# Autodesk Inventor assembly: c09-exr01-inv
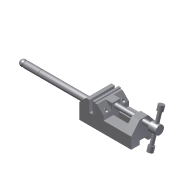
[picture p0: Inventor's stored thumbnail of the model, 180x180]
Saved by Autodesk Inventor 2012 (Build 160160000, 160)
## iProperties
Created: 2009-05
Part Number: c09-exr01-inv
Document SubType Name: Assembly
Designer: Sham
Author: Sham
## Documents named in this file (9)
- C:\Users\CadCim\Documents\SAILESH\inventor-2011-fact-prt\c09_inv_2011-prt\c09_inv_2012_prt\Exercises\c09_exr01_inv\c09-exr01-inv.iam
- C:\Users\CadCim\Documents\SAILESH\inventor-2011-fact-prt\c09_inv_2011-prt\c09_inv_2012_prt\Exercises\c09-exr01-inv\Base.ipt
- C:\Users\CadCim\Documents\SAILESH\inventor-2011-fact-prt\c09_inv_2011-prt\c09_inv_2012_prt\Exercises\c09-exr01-inv\Safety Handle.ipt
- C:\Users\CadCim\Documents\SAILESH\inventor-2011-fact-prt\c09_inv_2011-prt\c09_inv_2012_prt\Exercises\c09-exr01-inv\Jaw Face.ipt
- C:\Users\CadCim\Documents\SAILESH\inventor-2011-fact-prt\c09_inv_2011-prt\c09_inv_2012_prt\Exercises\c09-exr01-inv\Movable Jaw.ipt
- C:\Users\CadCim\Documents\SAILESH\inventor-2011-fact-prt\c09_inv_2011-prt\c09_inv_2012_prt\Exercises\c09-exr01-inv\Cap Screw.ipt
- C:\Users\CadCim\Documents\SAILESH\inventor-2011-fact-prt\c09_inv_2011-prt\c09_inv_2012_prt\Exercises\c09-exr01-inv\Clamp Screw Handle.ipt
- C:\Users\CadCim\Documents\SAILESH\inventor-2011-fact-prt\c09_inv_2011-prt\c09_inv_2012_prt\Exercises\c09-exr01-inv\Clamp Screw.ipt
- C:\Users\CadCim\Documents\SAILESH\inventor-2011-fact-prt\c09_inv_2011-prt\c09_inv_2012_prt\Exercises\c09-exr01-inv\Handle Stop.ipt
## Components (10 placed, 8 different names)
1. Base:1 — Mate:1, Mate:2, Mate:3, Flush:1
2. Safety Handle:1
3. Jaw Face:1 — Mate:1, Mate:4, Flush:1
4. Movable Jaw:1 — Mate:2, Mate:3, Mate:4, Insert:2, Insert:3, Insert:4
5. Cap Screw:1 — Insert:2
6. Cap Screw:2 — Insert:3
7. Clamp Screw:1 — Insert:4, Mate:6
8. Clamp Screw Handle:1 — Mate:6, Insert:5, Insert:6
9. Handle Stop:1 — Insert:6
10. Handle Stop:2 — Insert:5
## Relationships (11: Mate 5, Insert 5, Flush 1)
- Mate:1: Base:1 ↔ Jaw Face:1
- Mate:2: Base:1 ↔ Movable Jaw:1
- Mate:3: Base:1 ↔ Movable Jaw:1
- Mate:4: Jaw Face:1 ↔ Movable Jaw:1
- Insert:2: Movable Jaw:1 ↔ Cap Screw:1
- Insert:3: Movable Jaw:1 ↔ Cap Screw:2
- Insert:4: Movable Jaw:1 ↔ Clamp Screw:1
- Mate:6: Clamp Screw:1 ↔ Clamp Screw Handle:1
- Insert:5: Clamp Screw Handle:1 ↔ Handle Stop:2
- Insert:6: Clamp Screw Handle:1 ↔ Handle Stop:1
- Flush:1: Base:1 ↔ Jaw Face:1
